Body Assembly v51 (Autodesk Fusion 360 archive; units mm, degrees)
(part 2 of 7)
extrude "Extrude20" add of existing geometry blind 2.175 (= "0.125 in - 1 mm")
sketch "Sketch14" plane through (0, 0, 28) normal (0, 0, 1) x axis (-1, 0, 0)
  line L1 (0.8337, 14.8742) -> (-17.6263, 14.8742)
  line L2 (0.8337, -23.6158) -> (0.8337, 14.8742)
  line L3 (-17.6263, -23.6158) -> (0.8337, -23.6158)
  line L4 (-17.6263, 14.8742) -> (-17.6263, -23.6158)
  line L5 (-22.3888, -28.3783) -> (-22.3888, 19.6367)
  line L6 (5.5962, -28.3783) -> (-22.3888, -28.3783)
  line L7 (5.5962, 19.6367) -> (5.5962, -28.3783)
  line L8 (-22.3888, 19.6367) -> (5.5962, 19.6367)
  line L9 (-17.6963, 15.5831) -> (0.9037, 15.5831)
  line L10 (0.9037, 15.5831) -> (-17.6963, 15.5831)
  line L11 (-18.3963, -23.3708) -> (-18.3963, 14.6292)
  line L12 (-18.3963, -17.3601) -> (-18.3963, -23.3708)
  line L13 (-18.3963, -4.3708) -> (-18.3963, -17.3601)
  line L14 (-18.3963, 14.6292) -> (-18.3963, -4.3708)
  line L15 (1.6037, 14.6292) -> (1.6037, -23.3708)
  line L16 (1.6037, -4.3708) -> (1.6037, 14.6292)
  line L17 (1.6037, -17.3601) -> (1.6037, -4.3708)
  line L18 (1.6037, -23.3708) -> (1.6037, -17.3601)
  line L19 (-17.6963, -24.3248) -> (0.9037, -24.3248)
  line L20 (0.9037, -24.3248) -> (-17.6963, -24.3248)
  arc A1 centre (-17.3963, 14.6292) radius 1 clockwise from (-18.3963, 14.6292) to (-17.6963, 15.5831)
  arc A2 centre (-17.3963, 14.6292) radius 1 clockwise from (-18.3963, 14.6292) to (-17.6963, 15.5831)
  arc A3 centre (0.6037, 14.6292) radius 1 clockwise from (0.9037, 15.5831) to (1.6037, 14.6292)
  arc A4 centre (0.6037, 14.6292) radius 1 clockwise from (0.9037, 15.5831) to (1.6037, 14.6292)
  arc A5 centre (0.6037, -23.3708) radius 1 clockwise from (1.6037, -23.3708) to (0.9037, -24.3248)
  arc A6 centre (0.6037, -23.3708) radius 1 clockwise from (1.6037, -23.3708) to (0.9037, -24.3248)
  arc A7 centre (-17.3963, -23.3708) radius 1 clockwise from (-17.6963, -24.3248) to (-18.3963, -23.3708)
  arc A8 centre (-17.3963, -23.3708) radius 1 clockwise from (-17.6963, -24.3248) to (-18.3963, -23.3708)
extrude "Extrude21" add sketch "Sketch14" profile of L5 L6 L7 L8 A1 A2 L9 L10 L11 L12 L13 L14 A3 A4 L15 L16 L17 L18 A5 A6 L19 L20 A7 A8 along normal blind 13.0048
split "Split5"
extrude "Extrude22" add of existing geometry blind 2
remove_body "RemoveBody3"
copy_paste "CutPaste1"
copy_paste_bodies "CutPasteBodies1"
remove_instance "RemoveInstance2"
split "Split6"
remove_body "RemoveBody4"
combine "Combine1"
offset_faces "OffsetFaces3" distance 4.93 (= "0.1315944881889787 in + ( 1 / 16 ) * 1 in")
sketch "Sketch16" plane through (0, 0, 28) normal (0, 0, 1) x axis (-1, 0, 0)
  line L1 (5.5962, 24.5667) -> (5.5962, -33.3083)
  line L2 (-22.3888, 24.5667) -> (5.5962, 24.5667)
  line L3 (-22.3888, -33.3083) -> (-22.3888, 24.5667)
  line L4 (5.5962, -33.3083) -> (-22.3888, -33.3083)
  line L5 (0.8337, 14.8742) -> (-17.6263, 14.8742)
  line L6 (0.8337, -23.6158) -> (0.8337, 14.8742)
  line L7 (-17.6263, -23.6158) -> (0.8337, -23.6158)
  line L8 (-17.6263, 14.8742) -> (-17.6263, -23.6158)
  arc A1 centre (-3.4963, 20.4292) radius 2.1 clockwise from (-2.4963, 22.2758) to (-4.4963, 22.2758)
  circle C1 centre (-3.4963, 20.4292) radius 1.5
  concentric A1 C1
  dimension "d141" diameter C1 = 3
work_plane "WorkPlane5"
chamfer "Chamfer1" distance 6.35
split "Split7"
sketch "Sketch17" plane through (0, 0, 28) normal (0, 0, 1) x axis (-1, 0, 0)
  line L1 (0.8337, 14.8742) -> (-17.6263, 14.8742)
  line L2 (0.8337, -23.6158) -> (0.8337, 14.8742)
  line L3 (-17.6263, -23.6158) -> (0.8337, -23.6158)
  line L4 (-17.6263, 14.8742) -> (-17.6263, -23.6158)
  line L5 (5.5962, -26.9583) -> (-0.7538, -33.3083)
  line L6 (5.5962, 18.2167) -> (5.5962, -26.9583)
  line L7 (-0.7538, 24.5667) -> (5.5962, 18.2167)
  line L8 (-16.0388, 24.5667) -> (-0.7538, 24.5667)
  line L9 (-22.3888, 18.2167) -> (-16.0388, 24.5667)
  line L10 (-22.3888, -26.9583) -> (-22.3888, 18.2167)
  line L11 (-16.0388, -33.3083) -> (-22.3888, -26.9583)
  line L12 (-0.7538, -33.3083) -> (-16.0388, -33.3083)
  arc A1 centre (-3.4963, 20.4292) radius 2.1 clockwise from (-2.4963, 22.2758) to (-4.4963, 22.2758)
  circle C1 centre (-3.4963, 20.4292) radius 2.2
  concentric A1 C1
  dimension "d149" diameter C1 = 4.4
extrude "Extrude26" cut sketch "Sketch17" profile of C1 against normal blind 6
mirror "Mirror4" mirrorStitchTolerance 0.1016
mirror "Mirror5" mirrorStitchTolerance 0.1016
sketch "Sketch1" plane through (0, 0, 0) normal (0, 0, 1) x axis (1, 0, 0)
  circle C1 centre (0, 0) radius 2.45
  circle C2 centre (0, 0) radius 1.5
  circle C3 centre (0, 0) radius 1.95
  point P1 (0, 0)
  point P2 (0, 0)
  coincident P1 P2
  concentric C1 C2
  concentric C1 C3
  dimension "d1_2" diameter C1 = 4.9
  dimension "d2_2" diameter C2 = 3
  dimension "d3_2" diameter C3 = 3.9
extrude "Extrude1" new body sketch "Sketch1" distance 0.7 (= "( 1.4 / 2 ) * 1 mm") named "d4_2"
extrude "Extrude2" add sketch "Sketch1" profile of C2 C3 distance 3.3 (= "5 mm - 1.7 mm") named "d6_2"
extrude "Extrude3" of existing geometry blind 1.7 named "d9_2"
extrude "Extrude4" add of existing geometry blind 1.7 named "d11_2"
mirror "Mirror1" mirrorStitchTolerance 0.1 named "d14_1"
extrude "Extrude5" new body sketch "Sketch1" profile of C2 C3 distance 3 named "d15_1"
extrude "Extrude6" sketch "Sketch1" blind -1.8 named "d18_1"
mirror "Mirror2" mirrorStitchTolerance 0.1 named "d21_1"
move "Move1"
copy_paste "CutPaste4"
remove_body "RemoveBody1"
align "Align1"
mirror "Mirror3" mirrorStitchTolerance 0.1016
mirror "Mirror4" mirrorStitchTolerance 0.1016
base_feature "Base Feature1"
base_feature "Base Feature1"
base_feature "Base Feature1"
base_feature "Base Feature1"
base_feature "Base Feature1"
base_feature "Base Feature1"
copy_paste "CutPaste5"
remove_instance "RemoveInstance4"
align "Align1"
mirror "Mirror1" mirrorStitchTolerance 0.1016
mirror "Mirror2" mirrorStitchTolerance 0.1016
sketch "Sketch18" plane through (0, 0, -2.1658) normal (0, 0, -1) x axis (1, 0, 0)
  line L1 (0.7538, -33.3083) -> (-5.5962, -26.9583)
  line L2 (16.0388, -33.3083) -> (0.7538, -33.3083)
  line L3 (22.3888, -26.9583) -> (16.0388, -33.3083)
  line L4 (22.3888, 18.2167) -> (22.3888, -26.9583)
  line L5 (16.0388, 24.5667) -> (22.3888, 18.2167)
  line L6 (0.7538, 24.5667) -> (16.0388, 24.5667)
  line L7 (-5.5962, 18.2167) -> (0.7538, 24.5667)
  line L8 (-5.5962, -26.9583) -> (-5.5962, 18.2167)
  line L9 (-5.5962, -26.9583) -> (0.7538, -33.3083)
  line L10 (-5.5962, 18.2167) -> (-5.5962, -26.9583)
  line L11 (0.7538, 24.5667) -> (-5.5962, 18.2167)
  line L12 (3.6338, 24.5667) -> (0.7538, 24.5667)
  line L13 (3.6338, 13.4695) -> (3.6338, 24.5667)
  line L14 (13.1588, 24.5667) -> (13.1588, 13.4695)
  line L15 (16.0388, 24.5667) -> (13.1588, 24.5667)
  line L16 (22.3888, 18.2167) -> (16.0388, 24.5667)
  line L17 (22.3888, -26.9583) -> (22.3888, 18.2167)
  line L18 (16.0388, -33.3083) -> (22.3888, -26.9583)
  line L19 (13.1588, -33.3083) -> (16.0388, -33.3083)
  line L20 (13.1588, -22.6746) -> (13.1588, -33.3083)
  line L21 (15.8963, -9.7173) -> (15.8963, -19.8925)
  line L22 (12.2499, -6.0708) -> (15.8963, -9.7173)
  line L23 (4.5428, -6.0708) -> (12.2499, -6.0708)
  line L24 (0.8963, -9.7173) -> (4.5428, -6.0708)
  line L25 (0.8963, -19.8925) -> (0.8963, -9.7173)
  line L26 (3.6338, -33.3083) -> (3.6338, -22.6746)
  line L27 (0.7538, -33.3083) -> (3.6338, -33.3083)
  line L28 (-5.5962, -26.9583) -> (22.3888, 18.2167)
  line L29 (-5.5962, 18.2167) -> (22.3888, -26.9583)
  line L30 (-1.1287, -25.0083) -> (17.9213, -25.0083)
  line L31 (-1.1287, 16.2667) -> (-1.1287, -25.0083)
  line L32 (17.9213, 16.2667) -> (-1.1287, 16.2667)
  line L33 (17.9213, -25.0083) -> (17.9213, 16.2667)
  line L34 (-1.1287, 16.2667) -> (17.9213, -25.0083)
  line L35 (17.9213, 16.2667) -> (-1.1287, -25.0083)
  arc A1 centre (8.3963, 6.1292) radius 8.75 clockwise from (13.1588, 13.4695) to (3.6338, 13.4695)
  arc A2 centre (8.3963, -15.2505) radius 8.8203 clockwise from (15.8963, -19.8925) to (13.1588, -22.6746)
  arc A3 centre (8.3963, -15.2505) radius 8.8203 clockwise from (3.6338, -22.6746) to (0.8963, -19.8925)
  circle C1 centre (17.9213, 16.2667) radius 2.2
  point P20 (22.3888, 18.2167)
  point P34 (22.3888, 18.2167)
  point P11 (-5.5962, -26.9583)
  point P35 (-5.5962, -26.9583)
  point P21 (22.3888, -26.9583)
  point P36 (22.3888, -26.9583)
  point P12 (-5.5962, 18.2167)
  point P37 (-5.5962, 18.2167)
  point P38 (8.3963, -4.3708)
  point P43 (8.3963, -4.3708)
  point P42 (17.9213, 16.2667)
  point P44 (17.9213, 16.2667)
  point P39 (17.9213, -25.0083)
  point P41 (-1.1287, 16.2667)
  coincident P20 P34
  coincident P11 P35
  coincident P21 P36
  coincident P12 P37
  midpoint L29 P38
  horizontal L30
  perpendicular L30 L31
  parallel L30 L32
  parallel L31 L33
  coincident L34 P43
  coincident L35 P43
  coincident P38 P43
  coincident P42 P44
  dimension "d164" distance P39 P42 = 41.275
  dimension "d165" distance P41 P42 = 19.05
  dimension "d166" diameter C1 = 4.4
extrude "Extrude27" cut sketch "Sketch18" profile of C1 against normal blind 6
mirror "Mirror6" mirrorStitchTolerance 0.1016
mirror "Mirror7" mirrorStitchTolerance 0.1016
copy_paste_bodies "CopyPasteBodies1"
move "Move2"
align "Align2"
mirror "Mirror5" mirrorStitchTolerance 0.1016
mirror "Mirror6" mirrorStitchTolerance 0.1016
offset_faces "OffsetFaces4" distance 0.7937 (= "( 1 / 32 ) * 1 in")
delete_face "DeleteFace8"
delete_face "DeleteFace9"
delete_face "DeleteFace10"
delete_face "DeleteFace11"
delete_face "DeleteFace12"
delete_face "DeleteFace13"
delete_face "DeleteFace14"
delete_face "DeleteFace15"
chamfer "Chamfer2" distance 6.35
sketch "Sketch19" plane through (0, 0, 8.3168) normal (0, 0, 1) x axis (-1, 0, 0)
  line L1 (-16.8326, -34.1021) -> (-23.1826, -27.7521)
  line L2 (-13.1588, -34.1021) -> (-16.8326, -34.1021)
  line L3 (-13.1588, -22.6746) -> (-13.1588, -34.1021)
  line L4 (-15.8963, -9.7173) -> (-15.8963, -19.8925)
  line L5 (-12.2499, -6.0708) -> (-15.8963, -9.7173)
  line L6 (-4.5428, -6.0708) -> (-12.2499, -6.0708)
  line L7 (-0.8963, -9.7173) -> (-4.5428, -6.0708)
  line L8 (-0.8963, -19.8925) -> (-0.8963, -9.7173)
  line L9 (-3.6338, -34.1021) -> (-3.6338, -22.6746)
  line L10 (0.0399, -34.1021) -> (-3.6338, -34.1021)
  line L11 (6.3899, -27.7521) -> (0.0399, -34.1021)
  line L12 (6.3899, 19.0104) -> (6.3899, -27.7521)
  line L13 (0.0399, 25.3604) -> (6.3899, 19.0104)
  line L14 (-3.6338, 25.3604) -> (0.0399, 25.3604)
  line L15 (-3.6338, 13.4695) -> (-3.6338, 25.3604)
  line L16 (-13.1588, 25.3604) -> (-13.1588, 13.4695)
  line L17 (-16.8326, 25.3604) -> (-13.1588, 25.3604)
  line L18 (-23.1826, 19.0104) -> (-16.8326, 25.3604)
  line L19 (-23.1826, -27.7521) -> (-23.1826, 19.0104)
  line L20 (-14.7463, -14.6208) -> (-2.0463, -14.6208)
  arc A1 centre (-8.3963, -15.2505) radius 8.8203 clockwise from (-13.1588, -22.6746) to (-15.8963, -19.8925)
  arc A2 centre (-8.3963, -15.2505) radius 8.8203 clockwise from (-0.8963, -19.8925) to (-3.6338, -22.6746)
  arc A3 centre (-8.3963, 6.1292) radius 8.75 clockwise from (-3.6338, 13.4695) to (-13.1588, 13.4695)
  circle C1 centre (-8.3963, -14.6208) radius 4
  arc A4 centre (-7.6763, -14.8049) radius 9.6671 clockwise from (-15.8963, -19.8925) to (-15.8963, -9.7173)
  arc A5 centre (-9.1163, -14.8049) radius 9.6671 clockwise from (-0.8963, -9.7173) to (-0.8963, -19.8925)
  point P26 (-8.3963, -14.6208)
  point P29 (-8.3963, -14.6208)
  point P6 (-15.8963, -19.8925)
  point P31 (-15.8963, -19.8925)
  point P8 (-15.8963, -9.7173)
  point P30 (-15.8963, -9.7173)
  point P11 (-0.8963, -9.7173)
  point P34 (-0.8963, -9.7173)
  point P12 (-0.8963, -19.8925)
  point P33 (-0.8963, -19.8925)
  point P27 (-2.0463, -14.6208)
  point P28 (-14.7463, -14.6208)
  perpendicular L4 L20
  coincident P26 P29
  midpoint L20 P29
  coincident P6 P31
  coincident P8 P30
  coincident P11 P34
  coincident P12 P33
  tangent A1 A4
  tangent A2 A5
  dimension "d179" distance P27 P28 = 12.7
extrude "Extrude28" cut sketch "Sketch19" profile of L4 L8 A4 A5 against normal blind 2
sketch "Sketch20" plane through (0, 0, 26.4) normal (0, 0, 1) x axis (-1, 0, 0)
  line L1 (-17.6263, 14.8742) -> (-8.6921, 14.8742)
  line L2 (-17.6263, -23.6158) -> (-17.6263, 14.8742)
  line L3 (0.8337, -23.6158) -> (-17.6263, -23.6158)
  line L4 (0.8337, 14.8742) -> (0.8337, -23.6158)
  line L5 (-8.1005, 14.8742) -> (0.8337, 14.8742)
  line L6 (0.0837, -22.8658) -> (0.0837, -3.2059)
  line L7 (-16.8763, -22.8658) -> (0.0837, -22.8658)
  line L8 (-16.8763, -3.2059) -> (-16.8763, -22.8658)
  line L9 (-16.8763, 12.104) -> (-16.8763, -3.2059)
  line L10 (0.0837, 11.1729) -> (0.0837, -3.2059)
  arc A1 centre (-8.3963, 6.1292) radius 8.75 clockwise from (-8.1005, 14.8742) to (-1.4656, 0.788)
  arc A2 centre (-0.1579, -0.2198) radius 1.651 clockwise from (-0.8626, -1.7129) to (-1.4656, 0.788)
  arc A3 centre (-1.5673, -3.2059) radius 1.651 clockwise from (-0.8626, -1.7129) to (0.0837, -3.2059)
  arc A4 centre (-15.2253, -3.2059) radius 1.651 clockwise from (-16.8763, -3.2059) to (-15.93, -1.7129)
  arc A5 centre (-16.6347, -0.2198) radius 1.651 clockwise from (-15.327, 0.788) to (-15.93, -1.7129)
  arc A6 centre (-8.3963, 6.1292) radius 8.75 clockwise from (-15.327, 0.788) to (-8.6921, 14.8742)
  point P16 (-16.8763, -3.2059)
  point P21 (-16.8763, -3.2059)
  point P12 (0.0837, -3.2059)
  point P23 (0.0837, -3.2059)
  coincident P16 P21
  tangent A4 L9
  coincident P12 P23
  tangent A3 L10
extrude "Extrude29" cut sketch "Sketch20" profile of A1 A2 A3 A4 A5 A6 L9 L10 against normal blind 6.4008
extrude "Extrude30" cut of existing geometry blind -0.0036 (= "-1.417E-04 in")
component_from_bodies "Body->Comp1"
component_from_bodies "Body->Comp2"
component_from_bodies "Body->Comp3"
sketch "Sketch21" plane through (0, 0, 8.3168) normal (0, 0, 1) x axis (-1, 0, 0)
  line L1 (-3.6338, -34.1021) -> (-3.6338, -22.6746)
  line L2 (0.0399, -34.1021) -> (-3.6338, -34.1021)
  line L3 (6.3899, -27.7521) -> (0.0399, -34.1021)
  line L4 (6.3899, 19.0104) -> (6.3899, -27.7521)
  line L5 (0.0399, 25.3604) -> (6.3899, 19.0104)
  line L6 (-3.6338, 25.3604) -> (0.0399, 25.3604)
  line L7 (-3.6338, 13.4695) -> (-3.6338, 25.3604)
  line L8 (-13.1588, 25.3604) -> (-13.1588, 13.4695)
  line L9 (-16.8326, 25.3604) -> (-13.1588, 25.3604)
  line L10 (-23.1826, 19.0104) -> (-16.8326, 25.3604)
  line L11 (-23.1826, -27.7521) -> (-23.1826, 19.0104)
  line L12 (-16.8326, -34.1021) -> (-23.1826, -27.7521)
  line L13 (-13.1588, -34.1021) -> (-16.8326, -34.1021)
  line L14 (-13.1588, -22.6746) -> (-13.1588, -34.1021)
  line L15 (-12.2499, -6.0708) -> (-15.8963, -9.7173)
  line L16 (-4.5428, -6.0708) -> (-12.2499, -6.0708)
  line L17 (-0.8963, -9.7173) -> (-4.5428, -6.0708)
  line L18 (-0.8963, -9.7173) -> (-0.8963, -19.8925)
  line L19 (-4.5428, -6.0708) -> (-0.8963, -9.7173)
  line L20 (-12.2499, -6.0708) -> (-4.5428, -6.0708)
  line L21 (-15.8963, -9.7173) -> (-12.2499, -6.0708)
  line L22 (-15.8963, -19.8925) -> (-15.8963, -9.7173)
  line L23 (-13.1588, -34.1021) -> (-13.1588, -22.6746)
  line L24 (-3.6338, -34.1021) -> (-13.1588, -34.1021)
  line L25 (-3.6338, -22.6746) -> (-3.6338, -34.1021)
  arc A1 centre (-9.1163, -14.8049) radius 9.6671 clockwise from (-0.8963, -9.7173) to (-0.8963, -19.8925)
  arc A2 centre (-8.3963, -15.2505) radius 8.8203 clockwise from (-0.8963, -19.8925) to (-3.6338, -22.6746)
  arc A3 centre (-8.3963, 6.1292) radius 8.75 clockwise from (-3.6338, 13.4695) to (-13.1588, 13.4695)
  arc A4 centre (-8.3963, -15.2505) radius 8.8203 clockwise from (-13.1588, -22.6746) to (-15.8963, -19.8925)
  arc A5 centre (-7.6763, -14.8049) radius 9.6671 clockwise from (-15.8963, -19.8925) to (-15.8963, -9.7173)
  arc A6 centre (-8.3963, -15.2505) radius 8.5703 clockwise from (-1.1463, -19.8208) to (-15.6463, -19.8208)
  arc A7 centre (-8.3963, -15.2505) radius 8.8203 clockwise from (-3.6338, -22.6746) to (-13.1588, -22.6746)
  arc A8 centre (-8.3963, -15.2505) radius 8.8203 clockwise from (-13.1588, -22.6746) to (-15.8963, -19.8925)
  arc A9 centre (-8.3963, -15.2505) radius 8.8203 clockwise from (-0.8963, -19.8925) to (-3.6338, -22.6746)
  point P22 (-13.1588, -22.6746)
  point P32 (-13.1588, -22.6746)
  point P5 (-3.6338, -22.6746)
  point P31 (-3.6338, -22.6746)
  coincident P22 P32
  coincident P5 P31
  tangent A4 A7
extrude "Extrude1" add sketch "Sketch21" profile of L1 L14 A7 L23 L24 L25 against normal blind 5.207
move_face "MoveFace1"
position "Position5"
sketch "Sketch22" plane through (0, 0, 8.3168) normal (0, 0, 1) x axis (-1, 0, 0)
  line L1 (0.1537, -10.7673) -> (-3.4928, -7.1208)
  line L2 (0.1537, -18.4744) -> (0.1537, -10.7673)
  line L3 (-3.4928, -22.1208) -> (0.1537, -18.4744)
  line L4 (0.0399, -34.1021) -> (-16.8326, -34.1021)
  line L5 (6.3899, -27.7521) -> (0.0399, -34.1021)
  line L6 (6.3899, 19.0104) -> (6.3899, -27.7521)
  line L7 (0.0399, 25.3604) -> (6.3899, 19.0104)
  line L8 (-3.6338, 25.3604) -> (0.0399, 25.3604)
  line L9 (-3.6338, 13.4695) -> (-3.6338, 25.3604)
  line L10 (-13.1588, 25.3604) -> (-13.1588, 13.4695)
  line L11 (-16.8326, 25.3604) -> (-13.1588, 25.3604)
  line L12 (-23.1826, 19.0104) -> (-16.8326, 25.3604)
  line L13 (-23.1826, -27.7521) -> (-23.1826, 19.0104)
  line L14 (-16.8326, -34.1021) -> (-23.1826, -27.7521)
  line L15 (-10.2963, -17.1208) -> (-10.2963, -12.1208)
  line L16 (-6.4963, -17.1208) -> (-10.2963, -17.1208)
  line L17 (-6.4963, -12.1208) -> (-6.4963, -17.1208)
  line L18 (-10.2963, -12.1208) -> (-6.4963, -12.1208)
  line L19 (-3.6338, 25.3604) -> (-3.6338, 13.4695)
  line L20 (-13.1588, 25.3604) -> (-3.6338, 25.3604)
  line L21 (-13.1588, 13.4695) -> (-13.1588, 25.3604)
  line L22 (-6.4963, -12.1208) -> (-10.2963, -17.1208)
  line L23 (-6.4963, -17.1208) -> (-10.2963, -12.1208)
  line L24 (11.7059, -11.4458) -> (-28.4985, -11.4458)
  line L25 (11.7059, -17.7958) -> (11.7059, -11.4458)
  line L26 (-28.4985, -17.7958) -> (11.7059, -17.7958)
  line L27 (-28.4985, -11.4458) -> (-28.4985, -17.7958)
  line L28 (11.7059, -17.7958) -> (-28.4985, -11.4458)
  line L29 (-28.4985, -17.7958) -> (11.7059, -11.4458)
  line L30 (14.7067, 9.3042) -> (-31.4993, 9.3042)
  line L31 (14.7067, 2.9542) -> (14.7067, 9.3042)
  line L32 (-31.4993, 2.9542) -> (14.7067, 2.9542)
  line L33 (-31.4993, 9.3042) -> (-31.4993, 2.9542)
  line L34 (14.7067, 2.9542) -> (-31.4993, 9.3042)
  line L35 (-31.4993, 2.9542) -> (14.7067, 9.3042)
  arc A1 centre (-9.026, -14.6208) radius 8.8203 clockwise from (-13.668, -22.1208) to (-13.668, -7.1208)
  arc A2 centre (-8.5804, -15.3408) radius 9.6671 clockwise from (-13.668, -7.1208) to (-3.4928, -7.1208)
  arc A3 centre (-8.5804, -13.9008) radius 9.6671 clockwise from (-3.4928, -22.1208) to (-13.668, -22.1208)
  arc A4 centre (-8.3963, 6.1292) radius 8.75 clockwise from (-3.6338, 13.4695) to (-13.1588, 13.4695)
  arc A5 centre (-8.3963, 6.1292) radius 8.75 clockwise from (-3.6338, 13.4695) to (-13.1588, 13.4695)
  circle C1 centre (-8.3963, 6.1292) radius 8.75
  point P25 (-10.2963, -17.1208)
  point P33 (-10.2963, -17.1208)
  point P27 (-6.4963, -12.1208)
  point P34 (-6.4963, -12.1208)
  point P24 (-10.2963, -12.1208)
  point P35 (-10.2963, -12.1208)
  point P26 (-6.4963, -17.1208)
  point P36 (-6.4963, -17.1208)
  point P37 (-8.3963, -14.6208)
  point P42 (-8.3963, -14.6208)
  point P47 (-8.3963, 6.1292)
  point P30 (-8.3963, 6.1292)
  point P28 (-13.1588, 13.4695)
  point P43 (-31.4993, 9.3042)
  point P46 (-31.4993, 2.9542)
  point P38 (-28.4985, -11.4458)
  point P41 (-28.4985, -17.7958)
  coincident P25 P33
  coincident P27 P34
  coincident P24 P35
  coincident P26 P36
  midpoint L23 P37
  horizontal L24
  perpendicular L24 L25
  parallel L24 L26
  parallel L25 L27
  coincident L28 P42
  coincident L29 P42
  coincident P37 P42
  horizontal L30
  perpendicular L30 L31
  parallel L30 L32
  parallel L31 L33
  coincident L34 P47
  coincident L35 P47
  coincident P30 P47
  concentric A5 C1
  coincident P28 C1
  dimension "d189" distance P43 P46 = 6.35
  dimension "d190" distance P38 P41 = 6.35
extrude "Extrude2" add sketch "Sketch22" profile of L9 L10 L19 L20 L21 C1 against normal blind 7.3152
extrude "Extrude3" cut sketch "Sketch22" profile of A4 L13 A5 L30 L32 C1 against normal blind 7.3152
extrude "Extrude4" cut sketch "Sketch22" profile of A1 L13 L24 L26 against normal blind 5.207
extrude "Extrude5" add of existing geometry blind 0.0064 (= "2.520E-04 in")
extrude "Extrude6" add of existing geometry blind 0.007 (= "2.756E-04 in")
sketch "Sketch23" plane through (0, 0, 8.3168) normal (0, 0, 1) x axis (-1, 0, 0)
  line L1 (-23.1826, 2.9542) -> (-16.55, 2.9542)
  line L2 (-23.1826, -11.4458) -> (-23.1826, 2.9542)
  line L3 (-17.255, -11.4458) -> (-23.1826, -11.4458)
  line L4 (0.1537, -10.7673) -> (-3.4928, -7.1208)
  line L5 (0.1537, -18.4744) -> (0.1537, -10.7673)
  line L6 (-3.4928, -22.1208) -> (0.1537, -18.4744)
  line L7 (-23.1826, -17.7958) -> (-17.255, -17.7958)
  line L8 (-23.1826, -27.7521) -> (-23.1826, -17.7958)
  line L9 (-16.8326, -34.1021) -> (-23.1826, -27.7521)
  line L10 (0.0399, -34.1021) -> (-16.8326, -34.1021)
  line L11 (6.3899, -27.7521) -> (0.0399, -34.1021)
  line L12 (6.3899, 19.0104) -> (6.3899, -27.7521)
  line L13 (0.0399, 25.3604) -> (6.3899, 19.0104)
  line L14 (-16.8326, 25.3604) -> (0.0399, 25.3604)
  line L15 (-23.1826, 19.0104) -> (-16.8326, 25.3604)
  line L16 (-23.1826, 9.3042) -> (-23.1826, 19.0104)
  line L17 (-16.55, 9.3042) -> (-23.1826, 9.3042)
  line L18 (6.3899, -27.7521) -> (0.0399, -34.1021)
  line L19 (6.3899, 19.0104) -> (6.3899, -27.7521)
  line L20 (0.0399, 25.3604) -> (6.3899, 19.0104)
  line L21 (-16.8326, 25.3604) -> (0.0399, 25.3604)
  line L22 (-23.1826, 19.0104) -> (-16.8326, 25.3604)
  line L23 (-23.1826, -27.7521) -> (-23.1826, 19.0104)
  line L24 (-16.8326, -34.1021) -> (-23.1826, -27.7521)
  line L25 (0.0399, -34.1021) -> (-16.8326, -34.1021)
  line L26 (0.8337, 14.8742) -> (-17.6263, 14.8742)
  line L27 (0.8337, -23.6158) -> (0.8337, 14.8742)
  line L28 (-17.6263, -23.6158) -> (0.8337, -23.6158)
  line L29 (-17.6263, 14.8742) -> (-17.6263, -23.6158)
  arc A1 centre (-8.3963, 6.1292) radius 8.75 clockwise from (-16.55, 9.3042) to (-16.55, 2.9542)
  arc A2 centre (-9.026, -14.6208) radius 8.8203 clockwise from (-17.255, -11.4458) to (-13.668, -7.1208)
  arc A3 centre (-8.5804, -15.3408) radius 9.6671 clockwise from (-13.668, -7.1208) to (-3.4928, -7.1208)
  arc A4 centre (-8.5804, -13.9008) radius 9.6671 clockwise from (-3.4928, -22.1208) to (-13.668, -22.1208)
  arc A5 centre (-9.026, -14.6208) radius 8.8203 clockwise from (-13.668, -22.1208) to (-17.255, -17.7958)
  circle C1 centre (-3.4963, 20.4292) radius 2.2
  circle C2 centre (-13.2963, 20.4292) radius 2.2
  circle C3 centre (-3.4963, -29.1708) radius 2.2
  circle C4 centre (-13.2963, -29.1708) radius 2.2
extrude "Extrude7" cut sketch "Sketch23" profile of C1 C2 C3 C4 against normal blind 6
delete_face "DeleteFace1"
remove_body "RemoveBody2"
remove_body "RemoveBody3"
remove_body "RemoveBody4"
remove_body "RemoveBody5"
delete_face "DeleteFace1"
delete_face "DeleteFace2"
delete_face "DeleteFace3"
delete_face "DeleteFace4"
position "Position6"
sketch "Sketch24" plane through (0, 0, 28) normal (0, 0, 1) x axis (-1, 0, 0)
  line L1 (6.3899, -27.7521) -> (0.0399, -34.1021)
  line L2 (6.3899, 19.0104) -> (6.3899, -27.7521)
  line L3 (0.0399, 25.3604) -> (6.3899, 19.0104)
  line L4 (-16.8326, 25.3604) -> (0.0399, 25.3604)
  line L5 (-23.1826, 19.0104) -> (-16.8326, 25.3604)
  line L6 (-23.1826, -27.7521) -> (-23.1826, 19.0104)
  line L7 (-16.8326, -34.1021) -> (-23.1826, -27.7521)
  line L8 (0.0399, -34.1021) -> (-16.8326, -34.1021)
  line L9 (0.8337, 14.8742) -> (-17.6263, 14.8742)
  line L10 (0.8337, -23.6158) -> (0.8337, 14.8742)
  line L11 (-17.6263, -23.6158) -> (0.8337, -23.6158)
  line L12 (-17.6263, 14.8742) -> (-17.6263, -23.6158)
  circle C1 centre (-3.4963, -29.1708) radius 1.5
  circle C2 centre (-3.4963, -29.1708) radius 1.5
  concentric C1 C2
  dimension "d205" diameter C2 = 3
extrude "Extrude1" cut sketch "Sketch24" profile of C2 against normal blind 43.18
mirror "Mirror1" mirrorStitchTolerance 0.1016
mirror "Mirror2" mirrorStitchTolerance 0.1016
extrude "Extrude8" cut of existing geometry blind -25.4
sketch "Sketch1" plane through (0, 0, 0) normal (0, 0, 1) x axis (1, 0, 0)
  circle C1 centre (0, 0) radius 2.45
  circle C2 centre (0, 0) radius 1.5
  circle C3 centre (0, 0) radius 1.95
  point P1 (0, 0)
  point P2 (0, 0)
  coincident P1 P2
  concentric C1 C2
  concentric C1 C3
  dimension "d1_3" diameter C1 = 4.9
  dimension "d2_3" diameter C2 = 3
  dimension "d3_3" diameter C3 = 3.9
extrude "Extrude1" new body sketch "Sketch1" distance 0.7 (= "( 1.4 / 2 ) * 1 mm") named "d4_3"
extrude "Extrude2" add sketch "Sketch1" profile of C2 C3 distance 3.3 (= "5 mm - 1.7 mm") named "d6_3"
extrude "Extrude3" of existing geometry blind 1.7 named "d9_3"
extrude "Extrude4" add of existing geometry blind 1.7 named "d11_3"
mirror "Mirror1" mirrorStitchTolerance 0.1 named "d14_2"
extrude "Extrude5" new body sketch "Sketch1" profile of C2 C3 distance 3 named "d15_2"
extrude "Extrude6" sketch "Sketch1" blind -1.8 named "d18_2"
mirror "Mirror2" mirrorStitchTolerance 0.1 named "d21_2"
move "Move1"
remove_body "RemoveBody1"
extrude "Extrude9" cut of existing geometry blind -0.4826 (= "10 mm - 0.4127007874015741 in")
position "Position7"
mirror "Mirror3" mirrorStitchTolerance 0.1016
mirror "Mirror4" mirrorStitchTolerance 0.1016
copy_paste "CutPaste6"
offset_faces "OffsetFaces1" distance -3.175
delete_face "DeleteFace2"
delete_face "DeleteFace3"
delete_face "DeleteFace4"
chamfer "Chamfer1" distance 4.7625
remove_instance "RemoveInstance1"
offset_faces "OffsetFaces2" distance -0.2
sketch "Sketch25" plane through (0, 0, 1.008) normal (0, 0, 1) x axis (-1, 0, 0)
  line L1 (-20.0076, 9.3042) -> (-16.55, 9.3042)
  line L2 (-20.0076, 2.9542) -> (-20.0076, 9.3042)
  line L3 (-16.55, 2.9542) -> (-20.0076, 2.9542)
  line L4 (-20.0076, -11.4458) -> (-17.255, -11.4458)
  line L5 (-20.0076, -17.7958) -> (-20.0076, -11.4458)
  line L6 (-17.255, -17.7958) -> (-20.0076, -17.7958)
  line L7 (-3.4928, -22.1208) -> (-13.668, -22.1208)
  line L8 (0.1537, -18.4744) -> (-3.4928, -22.1208)
  line L9 (0.1537, -10.7673) -> (0.1537, -18.4744)
  line L10 (-3.4928, -7.1208) -> (0.1537, -10.7673)
  line L11 (-13.668, -7.1208) -> (-3.4928, -7.1208)
  line L12 (-20.0076, -17.7958) -> (-17.255, -17.7958)
  line L13 (-20.0076, -11.4458) -> (-20.0076, -17.7958)
  line L14 (-17.255, -11.4458) -> (-20.0076, -11.4458)
  line L15 (-17.255, -17.7958) -> (-17.255, -11.4458)
  line L16 (-20.0076, 2.9542) -> (-16.55, 2.9542)
  line L17 (-20.0076, 9.3042) -> (-20.0076, 2.9542)
  line L18 (-16.55, 9.3042) -> (-20.0076, 9.3042)
  line L19 (-16.55, 2.9542) -> (-16.55, 9.3042)
  arc A1 centre (-8.3963, 6.1292) radius 8.75 clockwise from (-16.55, 9.3042) to (-16.55, 2.9542)
  arc A2 centre (-9.026, -14.6208) radius 8.8203 clockwise from (-17.255, -11.4458) to (-13.668, -7.1208)
  arc A3 centre (-9.026, -14.6208) radius 8.8203 clockwise from (-13.668, -22.1208) to (-17.255, -17.7958)
  point P10 (-20.0076, -11.4458)
  point P20 (-20.0076, -11.4458)
  point P12 (-17.255, -17.7958)
  point P18 (-17.255, -17.7958)
  point P5 (-20.0076, 9.3042)
  point P24 (-20.0076, 9.3042)
  point P2 (-16.55, 2.9542)
  point P22 (-16.55, 2.9542)
  horizontal L12
  vertical L13
  horizontal L14
  vertical L15
  coincident P10 P20
  coincident P12 P18
  horizontal L16
  vertical L17
  horizontal L18
  vertical L19
  coincident P5 P24
  coincident P2 P22
extrude "Extrude10" cut sketch "Sketch25" profile of L1 L2 L3 L16 L17 L18 L19 against normal blind 8.89
extrude "Extrude11" cut sketch "Sketch25" profile of L4 L5 L6 L12 L13 L14 L15 distance 11.43
copy_paste "CutPaste1"
remove_instance "RemoveInstance8"
remove_instance "RemoveInstance9"
mirror_component "MirrorComponent2"
derived_instance "DerivedInstance2"
position "Position4"
position "Position5"
position "Position6"
position "Position7"
sketch "main sketch" plane through (0, -27.2, 0) normal (0, -1, 0) x axis (1, 0, 0)
  line L1 (-18.7031, 75.8108) -> (12.2732, 75.8108)
  line L2 (-3.2149, -51.1892) -> (-3.2149, 75.8108)
  line L3 (-52.3824, 37.6979) -> (-20.6556, 77.3722)
  line L4 (-16.7506, 74.2495) -> (-48.4774, 34.5752)
  line L5 (-50.4299, 36.1365) -> (-18.7031, 75.8108)
  line L6 (-5.3332, -40.5169) -> (-52.5482, 34.8088)
  line L7 (-48.3116, 37.4643) -> (-1.0967, -37.8614)
  line L8 (-3.2149, -39.1892) -> (-50.4299, 36.1365)
  line L9 (-51.9387, 49.1154) -> (-56.8979, 53.0812)
  line L10 (-25.9057, 52.0131) -> (-51.9387, 49.1154)
  line L11 (-130.2149, -51.1892) -> (-130.2149, 75.8108)
  line L12 (-130.2149, 75.8108) -> (-3.2149, 75.8108)
  line L13 (-130.2149, -51.1892) -> (-3.2149, -51.1892)
  line L14 (42.0475, 34.5752) -> (10.3208, 74.2495)
  line L15 (14.2257, 77.3722) -> (45.9525, 37.6979)
  line L16 (44, 36.1365) -> (12.2732, 75.8108)
  line L17 (-5.3332, -37.8614) -> (41.8817, 37.4643)
  line L18 (46.1183, 34.8088) -> (-1.0967, -40.5169)
  line L19 (-3.2149, -39.1892) -> (44, 36.1365)
  line L20 (45.5088, 49.1154) -> (19.4758, 52.0131)
  line L21 (50.4681, 53.0812) -> (45.5088, 49.1154)
  circle C1 centre (12.2732, 75.8108) radius 1.5
  circle C2 centre (-18.7031, 75.8108) radius 1.5
  circle C3 centre (-18.7031, 75.8108) radius 14
  circle C4 centre (-50.4299, 36.1365) radius 11.5
  arc A1 centre (-50.4299, 36.1365) radius 2.5 clockwise from (-48.4774, 34.5752) to (-52.3824, 37.6979)
  arc A2 centre (-18.7031, 75.8108) radius 2.5 clockwise from (-20.6556, 77.3722) to (-16.7506, 74.2495)
  arc A3 centre (12.7387, 22.1428) radius 76.2 clockwise from (-61.6577, 38.6238) to (-25.78, 87.8905)
  arc A4 centre (29.1955, -0.6206) radius 76.2 clockwise from (-39.9887, 31.3166) to (-11.2687, 63.9479)
  arc A5 centre (-3.2149, -39.1892) radius 2.5 clockwise from (-1.0967, -37.8614) to (-5.3332, -40.5169)
  arc A6 centre (-50.4299, 36.1365) radius 2.5 clockwise from (-52.5482, 34.8088) to (-48.3116, 37.4643)
  circle C5 centre (-3.2149, -39.1892) radius 9
  arc A7 centre (129.3236, 102.7516) radius 203.2 clockwise from (-9.3573, -45.7673) to (-61.2132, 32.1403)
  arc A8 centre (153.1884, 104.2222) radius 203.2 clockwise from (3.4186, -33.1067) to (-39.5235, 39.7834)
  circle C6 centre (12.2732, 75.8108) radius 14
  circle C7 centre (44, 36.1365) radius 11.5
  arc A9 centre (44, 36.1365) radius 2.5 clockwise from (45.9525, 37.6979) to (42.0475, 34.5752)
  arc A10 centre (12.2732, 75.8108) radius 2.5 clockwise from (10.3208, 74.2495) to (14.2257, 77.3722)
  arc A11 centre (-3.2149, -39.1892) radius 2.5 clockwise from (-1.0967, -40.5169) to (-5.3332, -37.8614)
  arc A12 centre (44, 36.1365) radius 2.5 clockwise from (41.8817, 37.4643) to (46.1183, 34.8088)
  arc A13 centre (-19.1685, 22.1428) radius 76.2 clockwise from (19.3502, 87.8905) to (55.2278, 38.6238)
  arc A14 centre (-35.6254, -0.6206) radius 76.2 clockwise from (4.8389, 63.9479) to (33.5588, 31.3166)
  arc A15 centre (-135.7535, 102.7516) radius 203.2 clockwise from (54.7833, 32.1403) to (2.9274, -45.7673)
  arc A16 centre (-159.6183, 104.2222) radius 203.2 clockwise from (33.0936, 39.7834) to (-9.8485, -33.1067)
  point P2 (12.2732, 75.8108)
  point P5 (12.2732, 75.8108)
  point P4 (-18.7031, 75.8108)
  point P6 (-18.7031, 75.8108)
  point P7 (-3.2149, 75.8108)
  point P14 (-18.7031, 75.8108)
  point P9 (-50.4299, 36.1365)
  point P15 (-50.4299, 36.1365)
  point P20 (-39.9887, 31.3166)
  point P19 (-11.2687, 63.9479)
  point P17 (-25.78, 87.8905)
  point P16 (-61.6577, 38.6238)
  point P26 (-50.4299, 36.1365)
  point P30 (-9.3573, -45.7673)
  point P29 (-61.2132, 32.1403)
  point P33 (3.4186, -33.1067)
  point P32 (-39.5235, 39.7834)
  point P35 (-56.8979, 53.0812)
  point P37 (-25.9057, 52.0131)
  point P40 (-130.2149, 75.8108)
  point P38 (-130.2149, 75.8108)
  point P41 (-130.2149, -51.1892)
  point P39 (-130.2149, -51.1892)
  point P48 (12.2732, 75.8108)
  point P27 (-3.2149, -39.1892)
  point P55 (-3.2149, -39.1892)
  point P49 (44, 36.1365)
  point P54 (44, 36.1365)
  point P43 (44, 36.1365)
  point P56 (19.3502, 87.8905)
  point P59 (4.8389, 63.9479)
  point P57 (55.2278, 38.6238)
  point P60 (33.5588, 31.3166)
  point P65 (33.0936, 39.7834)
  point P62 (54.7833, 32.1403)
  point P63 (2.9274, -45.7673)
  point P66 (-9.8485, -33.1067)
  point P68 (19.4758, 52.0131)
  point P70 (50.4681, 53.0812)
  point P36 (-51.9387, 49.1154)
  point P28 (-3.2149, -39.1892)
  point P69 (45.5088, 49.1154)
  concentric C2 C3
  coincident P2 P5
  coincident P4 P6
  midpoint L1 P7
  perpendicular L1 L2
  tangent L3 A1
  tangent A1 L4
  parallel L3 L4
  tangent L4 A2
  tangent L3 A2
  coincident P4 P14
  coincident P9 P15
  tangent C3 A3
  tangent C4 A3
  coincident C4 P20
  coincident C3 P19
  tangent C3 A4
  tangent C4 A4
  coincident C3 P17
  coincident C4 P16
  tangent L6 A5
  tangent A5 L7
  parallel L6 L7
  tangent L7 A6
  tangent L6 A6
  coincident P9 P26
  concentric A5 C5
  coincident C5 P30
  coincident C4 P29
  coincident C5 P33
  coincident C4 P32
  tangent C5 A8
  tangent C5 A7
  tangent C4 A8
  tangent C4 A7
  coincident A3 P35
  coincident A4 P37
  parallel L2 L11
  coincident L11 P40
  perpendicular L11 L12
  coincident P38 L12
  coincident L11 P41
  perpendicular L11 L13
  coincident P39 P41
  concentric C1 C6
  tangent L14 A9
  tangent A9 L15
  parallel L14 L15
  tangent L15 A10
  tangent L14 A10
  coincident P2 P48
  tangent L17 A11
  tangent A11 L18
  parallel L17 L18
  tangent L18 A12
  tangent L17 A12
  coincident P27 P55
  coincident P49 P54
  coincident P43 P54
  tangent C6 A13
  tangent C7 A13
  tangent C7 A14
  tangent C6 A14
  coincident C6 P56
  coincident C6 P59
  coincident C7 P57
  coincident C7 P60
  tangent C7 A16
  tangent C5 A16
  tangent C5 A15
  tangent C7 A15
  coincident C7 P65
  coincident C7 P62
  coincident C5 P63
  coincident C5 P66
  coincident A14 P68
  coincident A13 P70
  dimension "d55" distance L3 L4 = 5
  dimension "d57" distance P14 P15 = 50.8
  dimension "d58" radius A3 = 76.2
  dimension "d69" radius A4 = 76.2 (= "d58")
  dimension "d123" diameter C3 = 28
  dimension "d124" diameter C4 = 23
  dimension "d125" distance P26 P27 = 88.9
  dimension "d126" distance L6 L7 = 5 (= "d55")
  dimension "d127" diameter C5 = 18
  dimension "d128" radius A7 = 203.2 (= "d129")
  dimension "d129" radius A8 = 203.2
  dimension "d142" distance P35 P36 = 6.35
  dimension "d143" angle L9 L10 = 135
  dimension "d144" angle L5 L9 = 90
  dimension "d145" distance P36 P37 = 26.1938 (= "1 in + ( ( 1 / 32 ) * 1 in )")
  dimension "d146" distance P7 P40 = 127
  dimension "d147" distance P28 L11 = 127 (= "5 in + X")
  dimension "d186" distance P28 L12 = 115 (= "Linear Dimension-10")
  dimension "d201" distance P38 P39 = 127
  dimension "d230" distance L14 L15 = 5
  dimension "d231" diameter A11 = 5
  dimension "d232" distance P54 P55 = 88.9 (= "d125")
  dimension "d233" distance P48 P49 = 50.8 (= "d57")
  dimension "d234" diameter C7 = 23 (= "d124")
  dimension "d235" diameter C6 = 28 (= "d123")
  dimension "d236" radius A13 = 76.2 (= "d58")
  dimension "d237" radius A14 = 76.2 (= "d58")
  dimension "d238" radius A15 = 203.2 (= "d128")
  dimension "d239" radius A16 = 203.2 (= "d128")
  dimension "d245" angle L20 L21 = 135 (= "d143")
  dimension "d246" angle L16 L21 = 90 (= "d144")
  dimension "d247" distance P69 P70 = 6.35 (= "d142")
  dimension "d248" distance P68 P69 = 26.1938 (= "d145")
work_plane "WorkPlane1" PathDistance 0.5
copy_paste "CutPaste1"
copy_paste "CutPaste2"
copy_paste "CutPaste1"
extrude "Extrude1" new body sketch "main sketch" profile of C3 C4 A3 A4 A8 L9 L10 along normal blind 20.05 (= "0.75 in + gapfit1")
extrude "Extrude3" new body sketch "main sketch" profile of C4 A4 C5 A7 A8 A16 blind 6.35 from offset 6.85 (= "( 0.5 in + gapfit1 ) / 2")
extrude "Extrude4" new body sketch "main sketch" profile of C6 C7 A13 A14 A16 L20 L21 along normal blind 20.05 (= "0.75 in + gapfit1")
extrude "Extrude5" new body sketch "main sketch" profile of C5 A8 C7 A14 A15 A16 blind 6.35 from offset 6.85 (= "( 0.5 in + gapfit1 ) / 2")
extrude "Extrude6" cut sketch "main sketch" profile of C4 A3 A4 A8 L9 L10 C7 A13 A14 A16 L20 L21 blind 6.35 from offset 6.85 (= "( 0.5 in + gapfit1 ) / 2")
work_plane "WorkPlane3" AlongDistance 6.85 (= "0.25 in + gapfit2")
align "Align5"
align "Align6"
sketch "Sketch12" plane through (0, -20.35, 0) normal (0, 1, 0) x axis (-1, 0, 0)
  arc A1 centre (-12.7387, 22.1428) radius 76.2 clockwise from (25.78, 87.8905) to (61.6577, 38.6238)
  arc A2 centre (18.7031, 75.8108) radius 14 clockwise from (11.2687, 63.9479) to (25.78, 87.8905)
  arc A3 centre (-29.1955, -0.6206) radius 76.2 clockwise from (11.2687, 63.9479) to (39.9887, 31.3166)
  arc A4 centre (50.4299, 36.1365) radius 11.5 clockwise from (61.6577, 38.6238) to (39.9887, 31.3166)
  circle C1 centre (18.7031, 75.8108) radius 14
  point P3 (25.78, 87.8905)
  concentric A2 C1
  coincident P3 C1
extrude "Extrude31" cut sketch "Sketch12" profile of A2 C1 against normal blind 6.85 (magnitude of "-0.25 in - gapfit2")
fillet "Fillet2" radius 3.175
extrude "Extrude21" cut of existing geometry blind -0.5 (= "-gapfit1 / 2")
extrude "Extrude22" cut of existing geometry blind -0.5 (= "-gapfit1 / 2")
extrude "Extrude23" cut of existing geometry blind -0.5 (= "-gapfit1 / 2")
extrude "Extrude24" cut of existing geometry blind -0.5 (= "-gapfit1 / 2")
component_from_bodies "Body->Comp1"
component_from_bodies "Body->Comp2"
component_from_bodies "Body->Comp3"
component_from_bodies "Body->Comp4"
copy_paste "CutPaste1"
copy_paste "CutPaste2"
copy_paste "CutPaste3"
copy_paste "CutPaste4"
sketch "Sketch10" plane through (0, -33.55, 0) normal (0, -1, 0) x axis (1, 0, 0)
  line L1 (-3.2149, -39.1892) -> (-50.4299, 36.1365)
  line L2 (-3.2149, -39.1892) -> (44, 36.1365)
  line L3 (-22.3639, -32.4561) -> (-5.9307, -22.1556)
  line L4 (-0.4992, -22.1556) -> (15.9341, -32.4561)
  line L5 (-54.0229, 15.1486) -> (-34.8377, 27.1741)
  line L6 (47.593, 15.1486) -> (28.4078, 27.1741)
  line L7 (-28.622, 4.84) -> (-50.611, 17.2872)
  line L8 (-32.9107, -12.8368) -> (-28.622, 4.84)
  line L9 (-16.9311, -14.0621) -> (-32.9107, -12.8368)
  line L10 (-18.9252, -30.3007) -> (-16.9311, -14.0621)
  line L11 (22.1921, 4.84) -> (44.1811, 17.2872)
  line L12 (26.4808, -12.8368) -> (22.1921, 4.84)
  line L13 (10.5012, -14.0621) -> (26.4808, -12.8368)
  line L14 (12.4954, -30.3007) -> (10.5012, -14.0621)
  arc A1 centre (153.1884, 104.2222) radius 203.2 clockwise from (3.4186, -33.1067) to (-39.5235, 39.7834)
  arc A2 centre (129.3236, 102.7516) radius 203.2 clockwise from (-9.3573, -45.7673) to (-61.2132, 32.1403)
  circle C1 centre (-50.4299, 36.1365) radius 11.5
  circle C2 centre (-3.2149, -39.1892) radius 9
  arc A3 centre (-135.7535, 102.7516) radius 203.2 clockwise from (54.7833, 32.1403) to (2.9274, -45.7673)
  arc A4 centre (-159.6183, 104.2222) radius 203.2 clockwise from (33.0936, 39.7834) to (-9.8485, -33.1067)
  circle C3 centre (44, 36.1365) radius 11.5
  arc A5 centre (153.1884, 104.2222) radius 207.2 clockwise from (0.4703, -35.81) to (-43.317, 38.5149)
  arc A6 centre (129.3236, 102.7516) radius 199.2 clockwise from (-6.6274, -42.8437) to (-57.4625, 33.5303)
  arc A7 centre (-159.6183, 104.2222) radius 207.2 clockwise from (36.8871, 38.5149) to (-6.9002, -35.81)
  arc A8 centre (-135.7535, 102.7516) radius 199.2 clockwise from (51.0326, 33.5303) to (0.1975, -42.8437)
  point P21 (-5.9307, -22.1556)
  point P22 (-22.3639, -32.4561)
  point P23 (15.9341, -32.4561)
  point P24 (-0.4992, -22.1556)
  point P25 (-34.8377, 27.1741)
  point P26 (-54.0229, 15.1486)
  point P27 (28.4078, 27.1741)
  point P28 (47.593, 15.1486)
  point P41 (-50.611, 17.2872)
  point P42 (-28.622, 4.84)
  point P43 (-32.9107, -12.8368)
  point P44 (-16.9311, -14.0621)
  point P45 (-18.9252, -30.3007)
  point P46 (44.1811, 17.2872)
  point P47 (22.1921, 4.84)
  point P48 (26.4808, -12.8368)
  point P49 (10.5012, -14.0621)
  point P50 (12.4954, -30.3007)
  point P18 (-3.2149, -39.1892)
  point P20 (-3.2149, -39.1892)
  point P8 (-50.4299, 36.1365)
  point P16 (44, 36.1365)
  coincident A1 P21
  coincident A2 P22
  perpendicular L1 L3
  coincident A3 P23
  coincident A4 P24
  perpendicular L2 L4
  coincident A1 P25
  coincident A2 P26
  coincident A4 P27
  coincident A3 P28
  perpendicular L2 L6
  perpendicular L1 L5
  coincident A6 P41
  coincident L5 P41
  coincident A5 P42
  coincident A6 P43
  coincident A5 P44
  coincident L3 P45
  coincident A6 P45
  coincident L6 P46
  coincident A8 P46
  coincident A7 P47
  coincident A8 P48
  coincident A7 P49
  coincident A8 P50
  coincident L4 P50
  dimension "d338" distance P18 L3 = 15.875
  dimension "d339" distance P20 L4 = 15.875 (= "d338")
  dimension "d340" distance P8 L5 = 15.875
  dimension "d341" distance P16 L6 = 15.875 (= "d340")
  dimension "d342" = 4
  dimension "d343" = -4
  dimension "d344" = 4
  dimension "d345" = -4
  dimension "d346" distance L5 P42 = 22.225
  dimension "d347" distance L5 P43 = 34.925
  dimension "d348" distance L5 P44 = 44.45
  dimension "d349" distance L6 P47 = 22.225 (= "d346")
  dimension "d350" distance L6 P48 = 34.925 (= "d347")
  dimension "d351" distance L6 P49 = 44.45 (= "d348")
extrude "Extrude1" cut sketch "Sketch10" profile of L3 L4 L5 L6 A5 A6 A7 A8 L7 L8 L9 L10 L11 L12 L13 L14 distance -119.38
web "Web1" Thickness 4
sketch "Sketch11" plane through (0, -40.4, 0) normal (0, -1, 0) x axis (1, 0, 0)
  line L1 (10.5012, -14.0621) -> (26.4808, -12.8368)
  line L2 (12.4954, -30.3007) -> (10.5012, -14.0621)
  line L3 (26.4808, -12.8368) -> (22.1921, 4.84)
  line L4 (22.1921, 4.84) -> (44.1811, 17.2872)
  line L5 (44.1811, 17.2872) -> (31.8462, 25.0189)
  line L6 (2.9107, -24.293) -> (12.4954, -30.3007)
  arc A1 centre (-135.7535, 102.7516) radius 203.2 clockwise from (54.7833, 32.1403) to (2.9274, -45.7673)
  arc A2 centre (44, 36.1365) radius 11.5 clockwise from (33.0936, 39.7834) to (54.7833, 32.1403)
  arc A3 centre (-159.6183, 104.2222) radius 203.2 clockwise from (33.0936, 39.7834) to (-9.8485, -33.1067)
  arc A4 centre (-3.2149, -39.1892) radius 9 clockwise from (2.9274, -45.7673) to (-9.8485, -33.1067)
  arc A5 centre (-135.7535, 102.7516) radius 199.2 clockwise from (44.1811, 17.2872) to (12.4954, -30.3007)
  arc A6 centre (-159.6183, 104.2222) radius 207.2 clockwise from (31.8462, 25.0189) to (2.9107, -24.293)
web "Web1" Thickness 4
fillet "Fillet2" radius 1.5
chamfer "Chamfer1" distance 1.5875 (= "( 1 / 16 ) * 1 in")
sketch "Sketch13" plane through (0, 24.8582, 0) normal (0, 1, 0) x axis (-1, 0, 0)
  line L1 (37.9202, 66.7891) -> (25.2712, 55.623)
  line L2 (3.0497, 111.0882) -> (38.1993, 71.2706)
  line L3 (-14.0808, 100.2011) -> (-1.4317, 111.3672)
  line L4 (40.3005, 68.8903) -> (0.9485, 113.4684)
  line L5 (5.4814, 38.1532) -> (40.3005, 68.8903)
  line L6 (-33.8706, 82.7314) -> (5.4814, 38.1532)
  line L7 (0.9485, 113.4684) -> (-33.8706, 82.7314)
  line L8 (38.1993, 71.2706) -> (3.0497, 111.0882)
  line L9 (-1.4317, 111.3672) -> (-14.0808, 100.2011)
  line L10 (25.2712, 55.623) -> (37.9202, 66.7891)
  line L11 (-31.7694, 80.3511) -> (3.3802, 40.5335)
  line L12 (7.8616, 40.2544) -> (20.5107, 51.4206)
  line L13 (-18.8413, 95.9987) -> (-31.4904, 84.8326)
  line L14 (-34.5763, 82.7753) -> (5.4374, 37.4475)
  line L15 (0.9924, 114.1742) -> (-34.5763, 82.7753)
  line L16 (41.0062, 68.8464) -> (0.9924, 114.1742)
  line L17 (5.4374, 37.4475) -> (41.0062, 68.8464)
  line L18 (1.411, 120.8964) -> (-41.2985, 83.1939)
  line L19 (47.7284, 68.4278) -> (1.411, 120.8964)
  line L20 (5.0189, 30.7253) -> (47.7284, 68.4278)
  line L21 (-41.2985, 83.1939) -> (5.0189, 30.7253)
  line L22 (47.7284, 68.4278) -> (1.411, 120.8964)
  line L23 (57.2494, 76.8326) -> (47.7284, 68.4278)
  line L24 (10.932, 129.3012) -> (57.2494, 76.8326)
  line L25 (1.411, 120.8964) -> (10.932, 129.3012)
  line L26 (5.0189, 30.7253) -> (-41.2985, 83.1939)
  line L27 (-4.5021, 22.3205) -> (5.0189, 30.7253)
  line L28 (-50.8195, 74.7891) -> (-4.5021, 22.3205)
  line L29 (-41.2985, 83.1939) -> (-50.8195, 74.7891)
  arc A1 centre (-11.9796, 97.8209) radius 3.175 clockwise from (-14.3599, 95.7197) to (-14.0808, 100.2011)
  arc A2 centre (23.17, 58.0032) radius 3.175 clockwise from (25.2712, 55.623) to (20.7897, 55.902)
  point P19 (-1.4317, 111.3672)
  point P26 (-31.4904, 84.8326)
  point P6 (25.2712, 55.623)
  point P22 (3.3802, 40.5335)
  point P17 (38.1993, 71.2706)
  perpendicular L4 L5
  parallel L4 L6
  parallel L5 L7
  coincident L7 P19
  coincident L7 P26
  coincident P6 L5
  coincident L6 P22
  coincident L4 P17
  perpendicular L22 L23
  parallel L22 L24
  parallel L23 L25
  perpendicular L26 L27
  parallel L26 L28
  parallel L27 L29
  dimension "d373" = -0.5 (= "-gapfit3")
  dimension "d374" = -5.2625 (= "-gapfit3 - 0.1875 in")
  dimension "d394" distance L22 L24 = 12.7
  dimension "d395" distance L21 L28 = 12.7
extrude "Extrude32" new body sketch "Sketch13" profile of L14 L15 L16 L17 L18 L19 L20 L21 against normal blind 32.8676
fillet "Fillet3" radius 3.675 (= "0.125 in + gapfit3")
copy_paste_bodies "CutPasteBodies1"
component_from_bodies "Body->Comp1"
fillet "Fillet1" radius 8.4375 (= "0.125 in + 0.1875 in + gapfit3")
sketch "Sketch14" plane through (-18.0647, 0, 15.9469) normal (0.7497, 0, -0.6618) x axis (0, 1, 0)
  line L1 (16.8832, 68.1316) -> (16.8832, 61.7816)
  line L2 (18.032, 47.6316) -> (18.032, 41.2816)
  line L3 (14.8582, 41.2816) -> (18.032, 41.2816)
  line L4 (16.8832, 68.1316) -> (14.8582, 68.1316)
  line L5 (20.0319, 70.1316) -> (-8.0094, 70.1316)
  line L6 (20.0319, 39.2816) -> (20.0319, 70.1316)
  line L7 (-8.0094, 39.2816) -> (20.0319, 39.2816)
  line L8 (-8.0094, 70.1316) -> (-8.0094, 39.2816)
  line L9 (-8.0094, 81.2628) -> (-8.0094, 28.1503)
  horizontal L5
  vertical L6
  horizontal L7
  vertical L8
  collinear L8 L9
  dimension "d385" distance L2 L6 = 2
  dimension "d386" distance L4 L5 = 2
  dimension "d387" distance L3 L7 = 2
copy_paste "CutPaste4"
extrude "Extrude1" cut sketch "Sketch14" profile of L5 L6 L7 L8 against normal blind 91.44
sketch "Sketch15" plane through (59.3633, 0, 67.247) normal (0.6618, 0, 0.7497) x axis (0, 1, 0)
  line L1 (-8.0094, 72.6289) -> (-8.0094, 32.5339)
  line L2 (20.032, 61.4977) -> (-8.0094, 61.4977)
  line L3 (20.032, 43.6652) -> (20.032, 61.4977)
  line L4 (-8.0094, 43.6652) -> (20.032, 43.6652)
  line L5 (-8.0094, 61.4977) -> (-8.0094, 43.6652)
  line L6 (24.8582, 24.0964) -> (-8.0094, 24.0964)
  line L7 (-8.0094, 81.0664) -> (24.8582, 81.0664)
  point P4 (-8.0094, 61.4977)
  point P5 (20.032, 61.4977)
  horizontal L2
  vertical L3
  horizontal L4
  vertical L5
  coincident L1 P4
  dimension "d401" distance P4 P5 = 28.0414
  dimension "d403" distance L4 L6 = 19.5688
  dimension "d404" distance L2 L7 = 19.5688
extrude "Extrude3" cut sketch "Sketch15" profile of L1 L2 L3 L4 L5 against normal blind 180.34
fillet "Fillet2" radius 3.175
extrude "Extrude2" add sketch "Sketch13" profile of L4 L5 L6 L7 L8 L9 L10 L12 L13 L14 L15 L16 L17 L18 L19 L20 L21 L22 L23 L24 L25 L26 L27 L28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 along normal blind 4.7625
fillet "Fillet4" radius 12.7
work_plane "WorkPlane8"
offset_faces "OffsetFaces1" distance -9.9385
sketch "Sketch16" plane through (0, 0, 0) normal (0, 1, 0) x axis (1, 0, 0)
  circle C1 centre (12.2732, -75.8108) radius 10
  circle C2 centre (12.2732, -75.8108) radius 1.5
  circle C3 centre (12.2732, -68.8108) radius 1.5
  circle C4 centre (12.2732, -82.8108) radius 1.5
  circle C5 centre (19.2732, -75.8108) radius 1.5
  circle C6 centre (5.2732, -75.8108) radius 1.5
  circle C7 centre (-18.7031, -75.8108) radius 10
  circle C8 centre (-18.7031, -75.8108) radius 1.5
  circle C9 centre (-25.7031, -75.8108) radius 1.5
  circle C10 centre (-11.7031, -75.8108) radius 1.5
  circle C11 centre (-18.7031, -82.8108) radius 1.5
  circle C12 centre (-18.7031, -68.8108) radius 1.5
base_feature "Base Feature1"
base_feature "Base Feature1"
hole "Hole4" HoleDepth 93.98 HoleDiameter 3.5 (= "m3_diam") TipAngle 180
align "Align1"
sketch "Sketch17" plane through (0, -47.25, 0) normal (0, -1, 0) x axis (1, 0, 0)
  line L1 (-25.7031, 79.2172) -> (-22.7531, 77.514)
  line L2 (-28.6531, 77.514) -> (-25.7031, 79.2172)
  line L3 (-28.6531, 74.1077) -> (-28.6531, 77.514)
  line L4 (-25.7031, 72.4045) -> (-28.6531, 74.1077)
  line L5 (-22.7531, 74.1077) -> (-25.7031, 72.4045)
  line L6 (-22.7531, 77.514) -> (-22.7531, 74.1077)
  line L7 (-25.7031, 79.2172) -> (-25.7031, 75.8108)
  line L8 (5.2732, 79.2172) -> (5.2732, 75.8108)
  line L9 (2.3232, 77.514) -> (5.2732, 79.2172)
  line L10 (2.3232, 74.1077) -> (2.3232, 77.514)
  line L11 (5.2732, 72.4045) -> (2.3232, 74.1077)
  line L12 (8.2232, 74.1077) -> (5.2732, 72.4045)
  line L13 (8.2232, 77.514) -> (8.2232, 74.1077)
  line L14 (5.2732, 79.2172) -> (8.2232, 77.514)
  circle C1 centre (12.2732, 82.8108) radius 1.75
  circle C2 centre (12.2732, 68.8108) radius 1.75
  circle C3 centre (19.2732, 75.8108) radius 1.75
  point P5 (-25.7031, 75.8108)
  point P13 (-25.7031, 75.8108)
  point P14 (-25.7031, 75.8108)
  point P8 (-25.7031, 79.2172)
  point P15 (-25.7031, 79.2172)
  point P6 (5.2732, 75.8108)
  point P16 (5.2732, 75.8108)
  point P24 (5.2732, 75.8108)
  point P17 (5.2732, 79.2172)
  point P18 (5.2732, 79.2172)
  coincident P5 P13
  coincident P5 P14
  vertical L7
  coincident P8 L7
  coincident P8 P15
  coincident P6 P16
  vertical L8
  coincident P16 P24
  coincident P17 P18
  dimension "d438" distance L3 L6 = 5.9 (= "m3_locknut_width")
  dimension "d439" distance L10 L13 = 5.9 (= "m3_locknut_width")
extrude "Extrude1" cut sketch "Sketch17" profile of L9 L10 L11 L12 L13 L14 against normal blind 4
extrude "Extrude1" sketch "Sketch17" profile of L1 L2 L3 L4 L5 L6 blind -4
circular_pattern "C-Pattern1" TotalAngle 360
